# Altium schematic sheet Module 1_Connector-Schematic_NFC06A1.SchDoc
size A4; DocumentNumber: 3; SheetNumber: 3; SheetTotal: 5; PageSetup: Record=PageOptions¦CenterHorizontal=True¦CenterVertical=True¦PrintScale=0.73¦XCorrection=1.00¦YCorrection=1.00¦PrintKind=0¦BorderSize=5000000¦LeftOffset=0¦BottomOffset=0¦Orientation=2¦PaperLength=1000¦PaperWidth=1000¦Scale=100¦PaperSource=7¦PrintQuality=-3¦MediaType=1¦DitherType=10¦PrintScaleMode=1¦PaperKind=A4¦PaperIndex=9
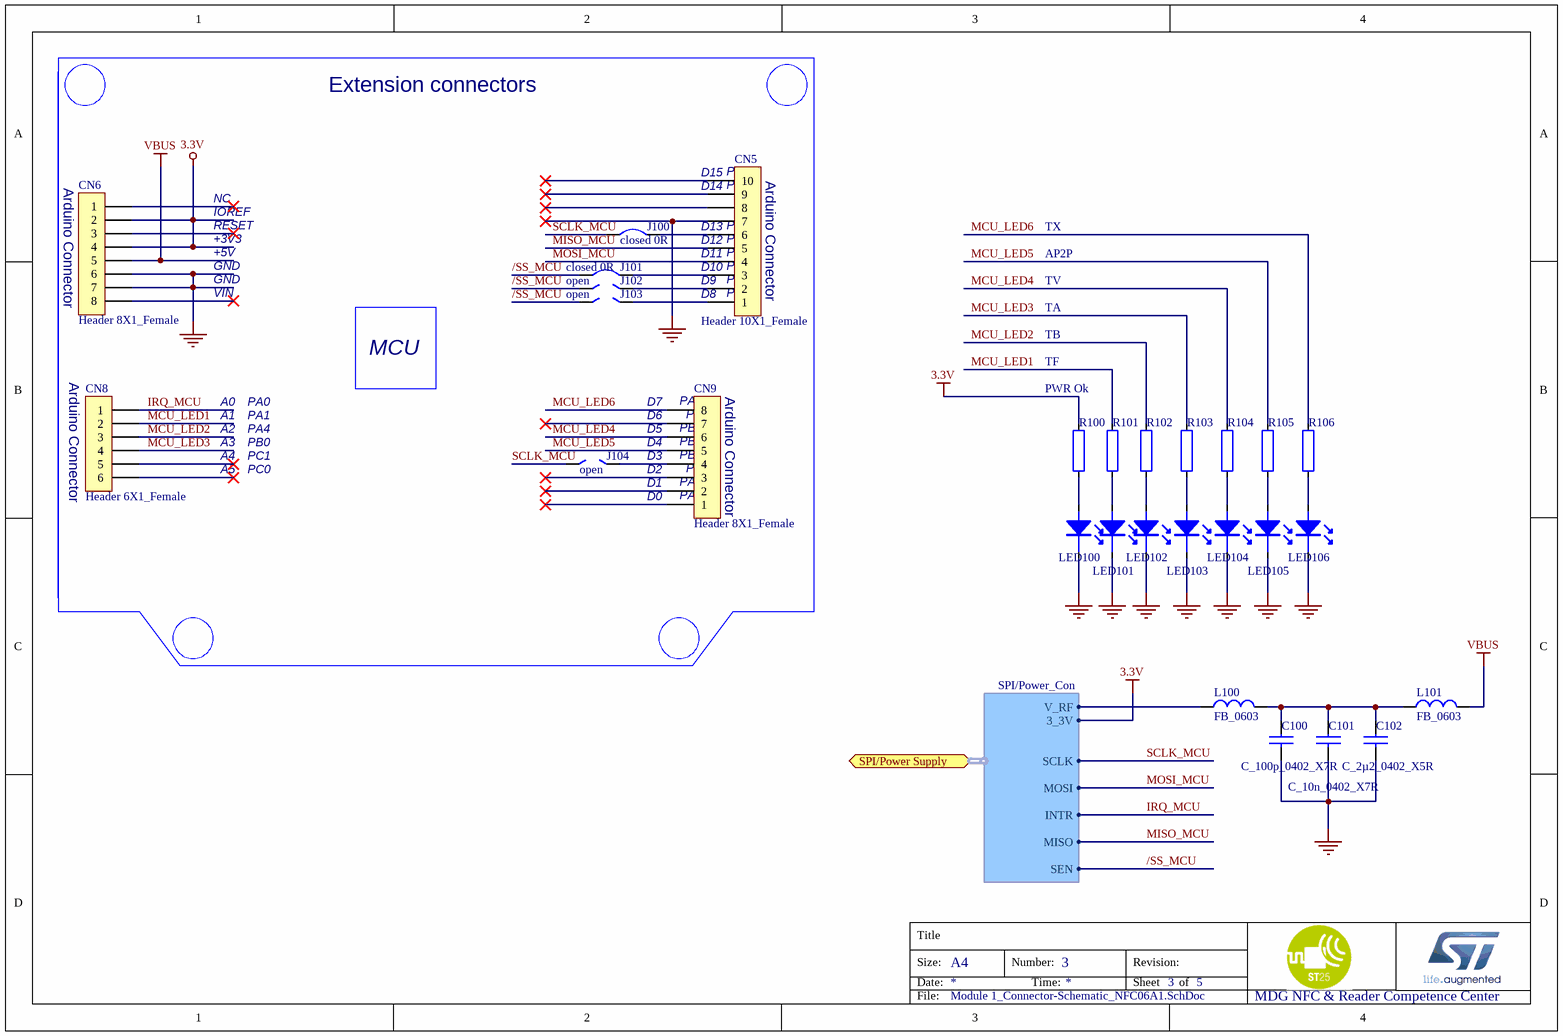
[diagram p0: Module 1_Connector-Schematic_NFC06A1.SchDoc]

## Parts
C100  C_100p_0402_X7R  [C0402]
C101  C_10n_0402_X7R  [C0402]
C102  C_2µ2_0402_X5R  [C0402]
CN5  Header 10X1_Female  [1*10P_FEMALE]
CN6  Header 8X1_Female  [1*8P_FEMALE]
CN8  Header 6X1_Female  [1*6P_FEMALE]
CN9  Header 8X1_Female  [1*8P_FEMALE]
J100  closed 0R  [JP2_SMD_closed]  (net tie)
J101  closed 0R  [JP2_SMD_closed]  (net tie)
J102  open  [JP2_SMD_open]  (net tie, no BOM)
J103  open  [JP2_SMD_open]  (net tie, no BOM)
J104  open  [JP2_SMD_open]  (net tie, no BOM)
L100  FB_0603  [L0603]
L101  FB_0603  [L0603]
LED100  Green  [D0603]  (value not drawn)
LED101  Blue  [D0603]  (value not drawn)
LED102  Blue  [D0603]  (value not drawn)
LED103  Blue  [D0603]  (value not drawn)
LED104  Blue  [D0603]  (value not drawn)
LED105  Blue  [D0603]  (value not drawn)
LED106  Blue  [D0603]  (value not drawn)
R100  680R  [R0402]  (value not drawn)
R101  1k  [R0402]  (value not drawn)
R102  1k  [R0402]  (value not drawn)
R103  1k  [R0402]  (value not drawn)
R104  1k  [R0402]  (value not drawn)
R105  1k  [R0402]  (value not drawn)
R106  1k  [R0402]  (value not drawn)

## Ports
SPI/Power Supply (harness SPI/Power_Con)

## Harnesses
SPI/Power_Con: V_RF, 3_3V, SEN, MISO, MOSI, SCLK, INTR

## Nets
3.3V: CN6.2 CN6.4 R100.2 ; port SPI/Power Supply.3_3V
GND: C100.2 C101.2 C102.2 CN5.7 CN6.6 CN6.7 LED100.2 LED101.2 LED102.2 LED103.2 LED104.2 LED105.2 LED106.2
VBUS: CN6.5 L101.1
/SS_MCU: J101.1 J102.1 J103.1 ; port SPI/Power Supply.SEN
IRQ_MCU: CN8.1 ; port SPI/Power Supply.INTR
MCU_LED1: CN8.2 R101.2
MCU_LED2: CN8.3 R102.2
MCU_LED3: CN8.4 R103.2
MCU_LED4: CN9.6 R104.2
MCU_LED5: CN9.5 R105.2
MCU_LED6: CN9.8 R106.2
MISO_MCU: CN5.5 ; port SPI/Power Supply.MISO
MOSI_MCU: CN5.4 ; port SPI/Power Supply.MOSI
SCLK_MCU: J100.1 J104.1 ; port SPI/Power Supply.SCLK
NetC100_1: C100.1 C101.1 C102.1 L100.1 L101.2
NetCN5_1: CN5.1 J103.2
NetCN5_2: CN5.2 J102.2
NetCN5_3: CN5.3 J101.2
NetCN5_6: CN5.6 J100.2
NetCN9_4: CN9.4 J104.2
NetL100_2: L100.2 ; port SPI/Power Supply.V_RF
NetLED100_1: LED100.1 R100.1
NetLED101_1: LED101.1 R101.1
NetLED102_1: LED102.1 R102.1
NetLED103_1: LED103.1 R103.1
NetLED104_1: LED104.1 R104.1
NetLED105_1: LED105.1 R105.1
NetLED106_1: LED106.1 R106.1

Not connected (* = marked no-connect by the designer): CN5 8* 9* 10*; CN6 1* 3* 8*; CN8 5* 6*; CN9 1* 2* 3* 7*

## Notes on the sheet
- Extension connectors
- (near CN5) D15
- (near CN5) PB8
- (near CN5) Arduino Connector
- (near CN6) Arduino Connector
- NC
- IOREF
- RESET
- +3V3
- D14
- D13
- D12
- (near CN5) PB9
- (near CN5) PA5
- (near CN5) PA6
- TX
- +5V
- GND
- VIN
- (near CN5) D8
- (near CN5) D9
- D10
- D11
- (near CN5) PA7
- (near CN5) PB6
- (near CN5) PC7
- (near CN5) PA9
- TA
- TV
- AP2P
- (near CN8) Arduino Connector
- MCU
- TF
- TB
- A0
- A1
- A2
- A3
- PA0
- PA1
- PA4
- PB0
- D4
- D5
- D6
- D7
- (near CN9) PA8
- (near CN9) PB4
- (near CN9) PB5
- (near CN9) PB10
- (near CN9) Arduino Connector
- PWR Ok
- A4
- A5
- PC1
- PC0
- D0
- D1
- (near J104) D2
- (near J104) D3
- (near CN9) PB3
- (near CN9) PA2
- (near CN9) PA3
- (near CN9) PA10

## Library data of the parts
C100 = C_100p_0402_X7R: 100p_X7R; Manufacturer: AVX; Manufacturer Part Number: 0402YC101KAT2A; 2nd Source: 0402, 0.01 µF, 25 V, ± 10%, X7R
C101 = C_10n_0402_X7R: 10n_x7R; Manufacturer: AVX; Manufacturer Part Number: 04023C103KAT2A; 2nd Source: 0402, 0.01 µF, 25 V, ± 10%, X7R
C102 = C_2µ2_0402_X5R: 2u2_X5R; Manufacturer: MURATA; Manufacturer Part Number: GRM155R60J225ME15D; 2nd Source: 0402, 2.2 µF, 6.3 V, ± 20%, X5R
CN5 = Header 10X1_Female: Header, 10-Pin, Single row,female; Manufacturer: Samtec; Manufacturer Part Number: SSQ-110-03-L-S; Comments: RECEPTACLE, 2.54MM, SINGLE ROW, 10WAY; 2nd source: doublesourcing allowed
CN6 CN9 = Header 8X1_Female: Header, 8-Pin, Single row,female; Manufacturer: Samtec; Manufacturer Part Number: SSQ-108-03-L-S; Comments: RECEPTACLE, 2.54MM, SINGLE ROW, 8WAY; 2nd source: doublesourcing allowed
CN8 = Header 6X1_Female: Header, 6-Pin, Single row,female; Manufacturer: Samtec; Manufacturer Part Number: SSQ-106-03-L-S; Comments: RECEPTACLE, 2.54MM, SINGLE ROW, 6 WAY; 2nd source: doublesourcing allowed
J100 J101 = solder_jumper_closed: 0R; Manufacturer: Multicomp; Manufacturer Part Number: MC00625W040210R
J102-J104 = solder_jumper_open
L100 L101 = FB_0603: Manufacturer: MURATA; Manufacturer Part Number: BLM18EG471SN1D
LED100 = LED-0603-Green: Manufacturer: Lite-On; Manufacturer Part Number: LTST-C190KGKT
LED101-LED106 = LED-0603-Blue: Manufacturer: Lite-On; Manufacturer Part Number: LTST-C190TBKT
R100 = R0402_680R: 680R, 0402; Manufacturer: Yageo; Manufacturer Part Number: RC0402JR-07680RL; 2nd Source: 680 Ohm ±5% 0.063W, 1/16W Chip Resistor 0402
R101-R106 = R0402_1k: 1k, 0402; Manufacturer: Panasonic; Manufacturer Part Number: ERJ2GEJ102X; 2nd Source: 1 kohm, 50 V, 0402, >100 mW, ± 5%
